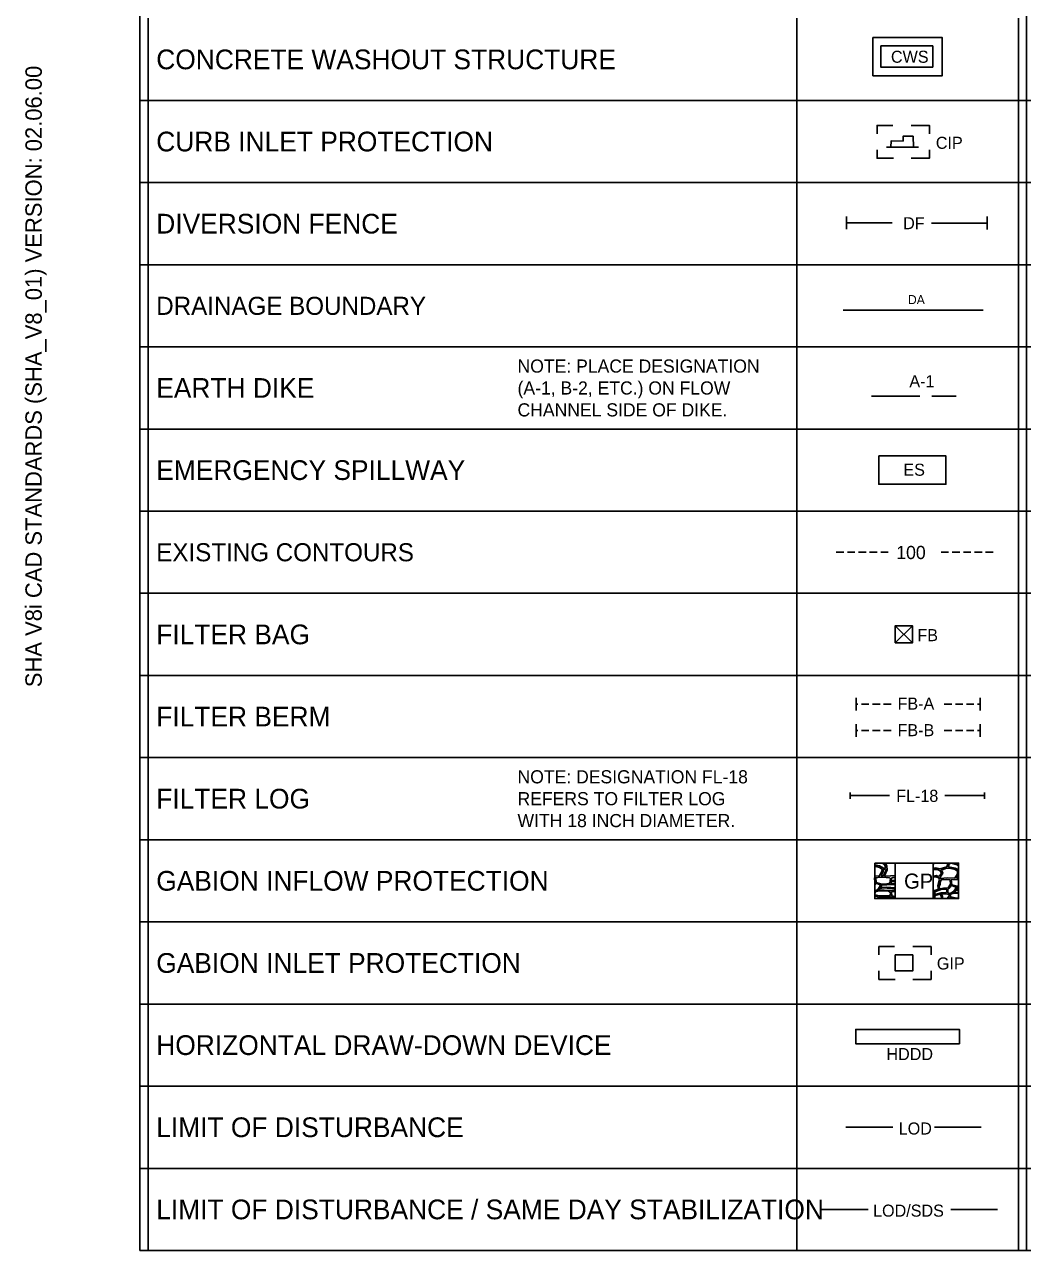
# Model space of a CAD drawing. Extents: x 1.3 to 34, y 0 to 22.5.
# Drawn here: x 1.3 to 7.38, y 7.83 to 15.29 of the extents above; entities that cross this region are included whole.
import ezdxf

# ---------------------------------------------------------------- set-up
doc = ezdxf.new("R2010")
doc.units = 0
for name, color, linetype in [('G-ANNO-SYMB', 7, 'Continuous'), ('G-ANNO-TABL', 7, 'Continuous'), ('G-USER-LINE', 7, 'Continuous'), ('G-USER-TEXT', 7, 'Continuous')]:
    doc.layers.add(name, color=color, linetype=linetype)

msp = doc.modelspace()

# ---------------------------------------------------------------- linework, layer by layer
at = {"layer": 'G-ANNO-SYMB'}
for p, q in [((6.5736, 14.5417), (6.5464, 14.5417)), ((6.7074, 14.5417), (6.7417, 14.5417)), ((6.3033, 14.08), (6.3033, 14.1192)), ((7.1596, 14.0789), (7.1596, 14.1181)), ((6.3033, 14.08), (6.5815, 14.08)), ((6.3033, 14.0407), (6.3033, 14.08)), ((6.82, 14.0789), (7.1596, 14.0789)), ((7.1596, 14.0397), (7.1596, 14.0789)), ((6.283, 13.5477), (7.1353, 13.5477)), ((6.4562, 13.025), (6.6031, 13.025)), ((6.6031, 13.025), (6.75, 13.025)), ((6.2866, 12.075), (6.2409, 12.075)), ((6.3544, 12.075), (6.3087, 12.075)), ((6.4222, 12.075), (6.3765, 12.075)), ((6.4901, 12.075), (6.4443, 12.075)), ((6.5579, 12.075), (6.5122, 12.075)), ((6.925, 12.075), (6.8793, 12.075)), ((6.9929, 12.075), (6.9471, 12.075)), ((7.0607, 12.075), (7.0149, 12.075)), ((7.1285, 12.075), (7.0828, 12.075)), ((7.1963, 12.075), (7.1506, 12.075)), ((6.6, 11.5228), (6.7044, 11.6272)), ((6.6, 11.6272), (6.7044, 11.5228)), ((6.3619, 11.1512), (6.3619, 11.1898)), ((6.3619, 11.1126), (6.3619, 11.1512)), ((6.3719, 11.1512), (6.3625, 11.1512)), ((6.4397, 11.1512), (6.394, 11.1512)), ((6.5075, 11.1512), (6.4618, 11.1512)), ((6.5753, 11.1512), (6.5296, 11.1512)), ((6.9441, 11.1512), (6.8983, 11.1512)), ((7.0119, 11.1512), (6.9662, 11.1512)), ((7.0797, 11.1512), (7.034, 11.1512)), ((7.1168, 11.1512), (7.1018, 11.1512)), ((7.1168, 11.1512), (7.1168, 11.1898)), ((7.1168, 11.1126), (7.1168, 11.1512)), ((6.3619, 10.9897), (6.3619, 11.0283)), ((6.3619, 10.9511), (6.3619, 10.9897)), ((6.3719, 10.9897), (6.3625, 10.9897)), ((6.4397, 10.9897), (6.394, 10.9897)), ((6.5075, 10.9897), (6.4618, 10.9897)), ((6.5753, 10.9897), (6.5296, 10.9897)), ((6.9441, 10.9897), (6.8983, 10.9897)), ((7.0119, 10.9897), (6.9662, 10.9897)), ((7.0797, 10.9897), (7.034, 10.9897)), ((7.1168, 10.9897), (7.1018, 10.9897)), ((7.1168, 10.9897), (7.1168, 11.0283)), ((7.1168, 10.9511), (7.1168, 10.9897)), ((6.3265, 10.6125), (6.3265, 10.5747)), ((7.1439, 10.6125), (7.1439, 10.5747)), ((6.3265, 10.5936), (6.5658, 10.5936)), ((6.9026, 10.5936), (7.1439, 10.5936)), ((6.5993, 10.1829), (6.5993, 9.9671)), ((6.8311, 10.1829), (6.8311, 9.9671)), ((6.3, 8.575), (6.5855, 8.575)), ((6.8387, 8.575), (7.1229, 8.575)), ((6.15, 8.075), (6.4355, 8.075)), ((6.9387, 8.075), (7.2229, 8.075))]:
    msp.add_line(p, q, dxfattribs=at)
for points in [[(6.464, 15.2081), (6.886, 15.2081), (6.886, 14.9753), (6.464, 14.9753)], [(6.5117, 15.1574), (6.8281, 15.1574), (6.8281, 15.0278), (6.5117, 15.0278)], [(6.5, 12.6613), (6.9083, 12.6613), (6.9083, 12.4887), (6.5, 12.4887)], [(6.6, 11.5228), (6.7044, 11.5228), (6.7044, 11.6272), (6.6, 11.6272)], [(6.475, 10.1829), (6.9854, 10.1829), (6.9854, 9.9671), (6.475, 9.9671)], [(6.8751, 10.0883), (6.8731, 10.097), (6.8896, 10.1222), (6.8817, 10.1403), (6.9061, 10.1494), (6.9297, 10.1519), (6.9649, 10.1432), (6.9798, 10.1329), (6.9785, 10.1176), (6.9628, 10.0908), (6.9173, 10.0929)], [(6.4809, 10.0935), (6.4844, 10.0646), (6.5173, 10.055), (6.5497, 10.0559), (6.5664, 10.0607), (6.5694, 10.0778), (6.5708, 10.0874), (6.5651, 10.0939), (6.5444, 10.0961), (6.5085, 10.0966)], [(6.5153, 10.1049), (6.5273, 10.1317), (6.5281, 10.1457), (6.5406, 10.1437), (6.543, 10.1379), (6.5277, 10.1053)], [(6.8706, 10.0269), (6.8951, 10.0313), (6.9223, 10.0321), (6.9364, 10.0544), (6.9346, 10.0803), (6.914, 10.0838), (6.8794, 10.0803), (6.8732, 10.0649), (6.8732, 10.0536), (6.8684, 10.0431)], [(6.4756, 9.9898), (6.5045, 9.9841), (6.5392, 9.9833), (6.5681, 9.9846), (6.5708, 9.9955), (6.5699, 10.0064), (6.5585, 10.0113), (6.5282, 10.0139), (6.4931, 10.0121), (6.4813, 10.0091), (6.4752, 9.9973)], [(6.8438, 9.9919), (6.8789, 10.0024), (6.9122, 10.0046), (6.9157, 10.0155), (6.9109, 10.0247), (6.8837, 10.0247), (6.8403, 10.0085)], [(6.9197, 10.0028), (6.9342, 9.9971), (6.9539, 10.0098), (6.9675, 10.0264), (6.9706, 10.0369), (6.9421, 10.0466), (6.932, 10.0339), (6.921, 10.0238)], [(6.6, 9.6236), (6.7071, 9.6236), (6.7071, 9.5264), (6.6, 9.5264)], [(6.9904, 9.0831), (6.3596, 9.0831), (6.3596, 9.1707), (6.9904, 9.1707)]]:
    msp.add_lwpolyline(points, close=True, dxfattribs=at)
for points in [[(6.49, 14.6219), (6.49, 14.6728), (6.5852, 14.6728)], [(6.6969, 14.6728), (6.8086, 14.6728), (6.8086, 14.6219)], [(6.5736, 14.5417), (6.711, 14.5417), (6.7092, 14.6067), (6.6477, 14.6067), (6.6477, 14.5778), (6.5754, 14.5796), (6.5736, 14.5417)], [(6.5898, 14.4731), (6.49, 14.4731), (6.49, 14.5247)], [(6.8086, 14.5247), (6.8086, 14.4731), (6.6969, 14.4731)], [(6.8234, 13.025), (6.9703, 13.025)], [(6.5205, 10.1829), (6.5343, 10.175), (6.5422, 10.1532), (6.5294, 10.1519), (6.5042, 10.166), (6.475, 10.172)], [(6.475, 10.1638), (6.5046, 10.1565), (6.5195, 10.1461), (6.5182, 10.1309), (6.5025, 10.1041), (6.475, 10.1053)], [(6.5718, 10.1047), (6.5546, 10.1028), (6.5356, 10.1049), (6.5509, 10.1412), (6.5488, 10.1635), (6.5404, 10.1829)], [(6.8311, 10.1528), (6.8445, 10.1544), (6.8743, 10.1473), (6.9144, 10.1597), (6.9202, 10.1791), (6.9176, 10.1829)], [(6.8341, 10.1829), (6.8321, 10.1762), (6.8311, 10.1751)], [(6.9854, 10.1411), (6.9645, 10.1527), (6.9243, 10.161), (6.9289, 10.1775), (6.9425, 10.182), (6.9765, 10.1721), (6.9854, 10.167)], [(6.9662, 10.1829), (6.9854, 10.1769)], [(6.475, 10.066), (6.476, 10.0677), (6.4743, 10.0935)], [(6.5993, 10.107), (6.5735, 10.1047)], [(6.5993, 10.096), (6.5856, 10.0954), (6.576, 10.0901), (6.575, 10.0796), (6.5993, 10.0777)], [(6.8311, 10.1036), (6.8499, 10.1069), (6.8644, 10.1007), (6.8809, 10.1213), (6.8743, 10.1366), (6.8569, 10.1445), (6.8311, 10.1438)], [(6.8311, 10.0971), (6.8499, 10.0999), (6.8644, 10.0933), (6.8688, 10.085)], [(6.8311, 10.0175), (6.8416, 10.016), (6.8638, 10.0241), (6.8604, 10.0452), (6.8688, 10.0835)], [(6.9854, 10.0831), (6.9688, 10.0833), (6.9412, 10.0803), (6.9447, 10.0514), (6.9776, 10.0418), (6.9854, 10.042)], [(6.9854, 10.092), (6.9756, 10.0916), (6.9854, 10.1135)], [(6.4738, 10.0104), (6.4936, 10.0231), (6.5072, 10.0397), (6.5102, 10.0502), (6.4817, 10.0598), (6.475, 10.0513)], [(6.5714, 10.0165), (6.5335, 10.0191), (6.498, 10.0178), (6.5076, 10.0288), (6.5304, 10.0318), (6.5501, 10.0309), (6.5718, 10.0295)], [(6.5714, 10.0523), (6.5484, 10.0506), (6.5195, 10.0498), (6.5142, 10.0432), (6.512, 10.0353), (6.5458, 10.0371), (6.5714, 10.0344)], [(6.5993, 10.051), (6.5735, 10.0522)], [(6.5735, 10.0344), (6.5952, 10.0326), (6.5993, 10.0314)], [(6.5735, 10.0165), (6.5952, 10.0182), (6.5993, 10.019)], [(6.5993, 10.0257), (6.5943, 10.0273), (6.5736, 10.0294)], [(6.5993, 10.0718), (6.5779, 10.0729), (6.575, 10.0695), (6.575, 10.0599), (6.5993, 10.0578)], [(6.5993, 10.0115), (6.5972, 10.011), (6.577, 10.0076), (6.5784, 9.9831), (6.5993, 9.9801)], [(6.8311, 9.975), (6.8335, 9.9747), (6.8383, 9.9915), (6.8344, 10.0083), (6.8311, 10.0091)], [(6.9854, 10.0005), (6.9535, 9.9989), (6.9416, 9.9958), (6.9355, 9.984), (6.9359, 9.9766), (6.9649, 9.9709), (6.9854, 9.9704)], [(6.9854, 10.0056), (6.9583, 10.0046), (6.9679, 10.0155), (6.9854, 10.0179)], [(6.9854, 10.0367), (6.9798, 10.0365), (6.9745, 10.0299), (6.9723, 10.0221), (6.9854, 10.0227)], [(6.4975, 9.9671), (6.4958, 9.9784), (6.4769, 9.9846), (6.475, 9.9844)], [(6.5718, 9.9765), (6.5458, 9.9776), (6.5054, 9.978), (6.5059, 9.9671)], [(6.5993, 9.9728), (6.5736, 9.9765)], [(6.8826, 9.9671), (6.8796, 9.9829), (6.8724, 9.9929), (6.844, 9.9853), (6.8392, 9.9665)], [(6.9167, 9.9671), (6.9289, 9.9827), (6.9285, 9.9914), (6.9083, 9.9963), (6.8811, 9.9954), (6.8872, 9.9801), (6.8889, 9.9671)], [(6.9501, 9.9671), (6.9372, 9.9713), (6.9271, 9.9704), (6.9241, 9.9671)], [(6.5002, 9.6236), (6.5002, 9.6745), (6.5954, 9.6745)], [(6.7071, 9.6745), (6.8188, 9.6745), (6.8188, 9.6236)], [(6.6, 9.4749), (6.5002, 9.4749), (6.5002, 9.5264)], [(6.8188, 9.5264), (6.8188, 9.4749), (6.7071, 9.4749)]]:
    msp.add_lwpolyline(points, dxfattribs=at)
at = {"layer": 'G-ANNO-TABL'}
for p, q in [((2, 14.825), (18.2, 14.825)), ((2, 14.325), (18.2, 14.325)), ((2, 13.825), (18.2, 13.825)), ((2, 13.325), (18.2, 13.325)), ((2, 12.825), (18.2, 12.825)), ((2, 12.325), (18.2, 12.325)), ((2, 11.825), (18.2, 11.825)), ((2, 11.325), (18.2, 11.325)), ((2, 10.825), (18.2, 10.825)), ((2, 10.325), (18.2, 10.325)), ((2, 9.825), (18.2, 9.825)), ((2, 9.325), (18.2, 9.325)), ((2, 8.825), (18.2, 8.825)), ((2, 8.325), (18.2, 8.325)), ((2, 7.825), (18.2, 7.825))]:
    msp.add_line(p, q, dxfattribs=at)
msp.add_lwpolyline([(2, 7.825), (7.4, 7.825), (7.4, 19.825), (2, 19.825)], close=True, dxfattribs=at)
at = {"layer": 'G-USER-LINE'}
for p, q in [((2.05, 14.825), (2.05, 15.325)), ((6, 14.825), (6, 15.325)), ((7.35, 14.825), (7.35, 15.325)), ((2.05, 14.325), (2.05, 14.825)), ((6, 14.825), (2.05, 14.825)), ((7.35, 14.825), (6, 14.825)), ((6, 14.325), (6, 14.825)), ((7.35, 14.325), (7.35, 14.825)), ((2.05, 13.825), (2.05, 14.325)), ((6, 14.325), (2.05, 14.325)), ((7.35, 14.325), (6, 14.325)), ((6, 13.825), (6, 14.325)), ((7.35, 13.825), (7.35, 14.325)), ((2.05, 13.325), (2.05, 13.825)), ((6, 13.825), (2.05, 13.825)), ((7.35, 13.825), (6, 13.825)), ((6, 13.325), (6, 13.825)), ((7.35, 13.325), (7.35, 13.825)), ((2.05, 12.825), (2.05, 13.325)), ((6, 13.325), (2.05, 13.325)), ((7.35, 13.325), (6, 13.325)), ((6, 12.825), (6, 13.325)), ((7.35, 12.825), (7.35, 13.325)), ((2.05, 12.325), (2.05, 12.825)), ((6, 12.825), (2.05, 12.825)), ((7.35, 12.825), (6, 12.825)), ((6, 12.325), (6, 12.825)), ((7.35, 12.325), (7.35, 12.825)), ((2.05, 11.825), (2.05, 12.325)), ((6, 12.325), (2.05, 12.325)), ((7.35, 12.325), (6, 12.325)), ((6, 11.825), (6, 12.325)), ((7.35, 11.825), (7.35, 12.325)), ((2.05, 11.325), (2.05, 11.825)), ((6, 11.825), (2.05, 11.825)), ((7.35, 11.825), (6, 11.825)), ((6, 11.325), (6, 11.825)), ((7.35, 11.325), (7.35, 11.825)), ((6, 11.325), (2.05, 11.325)), ((2.05, 10.825), (2.05, 11.325)), ((7.35, 11.325), (6, 11.325)), ((6, 10.825), (6, 11.325)), ((7.35, 10.825), (7.35, 11.325)), ((2.05, 10.325), (2.05, 10.825)), ((6, 10.825), (2.05, 10.825)), ((6, 10.325), (6, 10.825)), ((7.35, 10.825), (6, 10.825)), ((7.35, 10.325), (7.35, 10.825)), ((2.05, 9.825), (2.05, 10.325)), ((6, 10.325), (2.05, 10.325)), ((7.35, 10.325), (6, 10.325)), ((6, 9.825), (6, 10.325)), ((7.35, 9.825), (7.35, 10.325)), ((2.05, 9.325), (2.05, 9.825)), ((6, 9.825), (2.05, 9.825)), ((7.35, 9.825), (6, 9.825)), ((6, 9.325), (6, 9.825)), ((7.35, 9.325), (7.35, 9.825)), ((2.05, 8.825), (2.05, 9.325)), ((6, 9.325), (2.05, 9.325)), ((7.35, 9.325), (6, 9.325)), ((6, 8.825), (6, 9.325)), ((7.35, 8.825), (7.35, 9.325)), ((2.05, 8.325), (2.05, 8.825)), ((6, 8.825), (2.05, 8.825)), ((7.35, 8.825), (6, 8.825)), ((6, 8.325), (6, 8.825)), ((7.35, 8.325), (7.35, 8.825)), ((6, 8.325), (2.05, 8.325)), ((2.05, 7.825), (2.05, 8.325)), ((6, 8.325), (2.05, 8.325)), ((7.35, 8.325), (6, 8.325)), ((7.35, 8.325), (6, 8.325)), ((6, 7.825), (6, 8.325)), ((7.35, 7.825), (7.35, 8.325)), ((6, 7.825), (2.05, 7.825)), ((7.35, 7.825), (6, 7.825))]:
    msp.add_line(p, q, dxfattribs=at)

# ---------------------------------------------------------------- texts
at = {"layer": 'G-ANNO-SYMB'}
for s, height, p in [('CWS', 0.07344, (6.574, 15.0544)), ('CIP', 0.07344, (6.8473, 14.5305)), ('DF', 0.07344, (6.6483, 14.0412)), ('DA', 0.05508, (6.6778, 13.5852)), ('A-1', 0.07344, (6.6862, 13.0794)), ('ES', 0.07344, (6.6499, 12.5407)), ('100', 0.08035, (6.6063, 12.0335)), ('FB', 0.07344, (6.7351, 11.5338)), ('FB-A', 0.07344, (6.6141, 11.1171)), ('FB-B', 0.07344, (6.6141, 10.9555)), ('FL-18', 0.07344, (6.6058, 10.5556)), ('GP', 0.0918, (6.654, 10.0273)), ('GIP', 0.07344, (6.8534, 9.5353)), ('HDDD', 0.07344, (6.5465, 8.9838)), ('LOD', 0.07344, (6.6212, 8.5308)), ('LOD/SDS', 0.07344, (6.4652, 8.0308))]:
    msp.add_text(s, height=height, dxfattribs=at).set_placement(p)
at = {"layer": 'G-ANNO-TABL'}
for s, height, p in [('CONCRETE WASHOUT STRUCTURE', 0.12, (2.1, 15.015)), ('CURB INLET PROTECTION ', 0.12, (2.1, 14.515)), ('DIVERSION FENCE', 0.12, (2.1, 14.015)), ('DRAINAGE BOUNDARY', 0.11, (2.1, 13.52)), ('NOTE: PLACE DESIGNATION', 0.08, (4.3, 13.1683)), ('EARTH DIKE', 0.12, (2.1, 13.015)), ('(A-1, B-2, ETC.) ON FLOW', 0.08, (4.3, 13.035)), ('CHANNEL SIDE OF DIKE.', 0.08, (4.3, 12.9017)), ('EMERGENCY SPILLWAY', 0.12, (2.1, 12.515)), ('EXISTING CONTOURS', 0.11, (2.1, 12.02)), ('FILTER BAG', 0.12, (2.1, 11.515)), ('FILTER BERM', 0.12, (2.1, 11.015)), ('NOTE: DESIGNATION FL-18', 0.08, (4.3, 10.6683)), ('FILTER LOG', 0.12, (2.1, 10.515)), ('REFERS TO FILTER LOG', 0.08, (4.3, 10.535)), ('WITH 18 INCH DIAMETER.', 0.08, (4.3, 10.4017)), ('GABION INFLOW PROTECTION', 0.12, (2.1, 10.015)), ('GABION INLET PROTECTION', 0.12, (2.1, 9.515)), ('HORIZONTAL DRAW-DOWN DEVICE', 0.12, (2.1, 9.015)), ('LIMIT OF DISTURBANCE', 0.12, (2.1, 8.515)), ('LIMIT OF DISTURBANCE / SAME DAY STABILIZATION', 0.12, (2.1, 8.015))]:
    msp.add_text(s, height=height, dxfattribs=at).set_placement(p)
at = {"layer": 'G-USER-TEXT'}
msp.add_text('SHA V8i CAD STANDARDS (SHA_V8_01) VERSION: 02.06.00 ', height=0.1, rotation=90, dxfattribs=at).set_placement((1.403, 11.2535))

doc.saveas('drawing.dxf')
